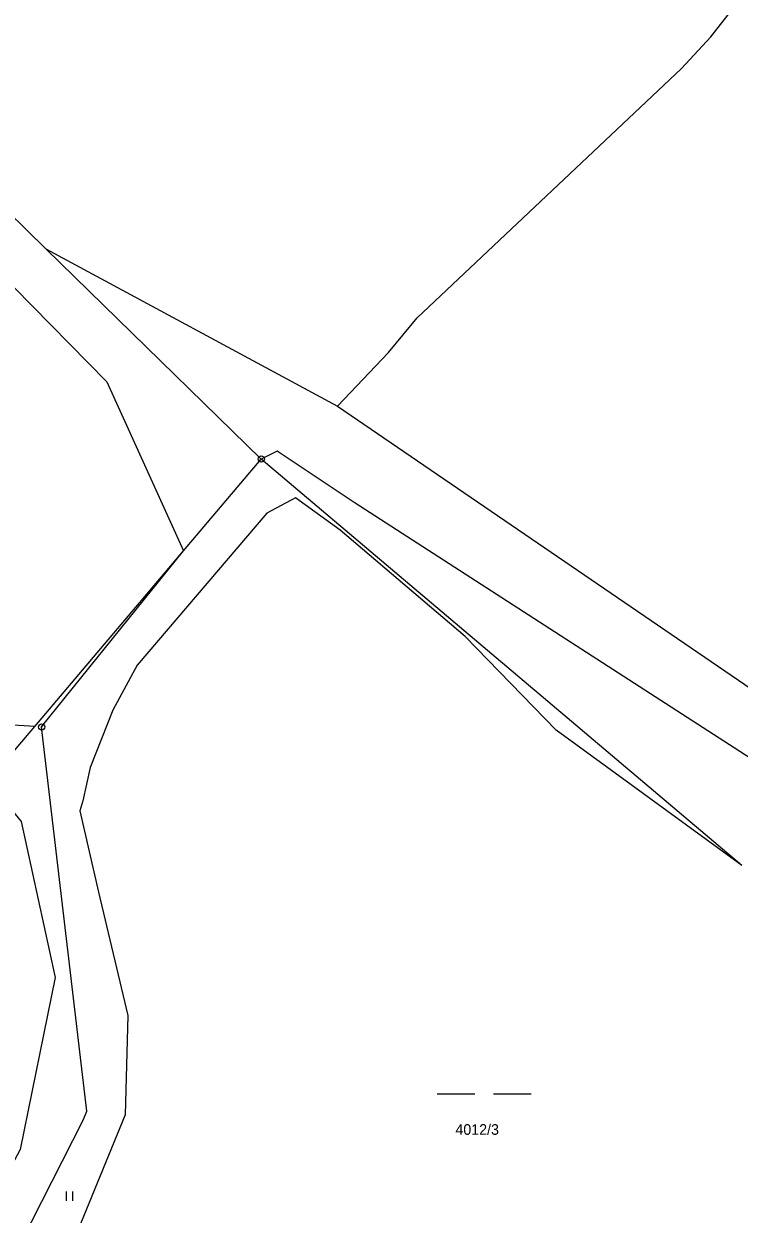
# Model space of a CAD drawing. Extents: x -733394 to -722299, y -1082822 to -1075049.
# Drawn here: x -727518.4 to -727404.2, y -1080319.1 to -1080129.1 of the extents above; entities that cross this region are included whole.
import ezdxf

# ---------------------------------------------------------------- set-up
doc = ezdxf.new("R2010")
doc.units = 0
for name, color, linetype in [('Hranice parcel', 7, 'Continuous'), ('Parcelní čísla', 7, 'Continuous'), ('Značky bodu BP', 7, 'Continuous'), ('Značky kultur', 7, 'Continuous')]:
    doc.layers.add(name, color=color, linetype=linetype)

msp = doc.modelspace()

# ---------------------------------------------------------------- linework, layer by layer
at = {"layer": 'Hranice parcel'}
for p, q in [((-727514.92, -1080165), (-727468.36, -1080190.16)), ((-727480.51, -1080198.57), (-727514.92, -1080165)), ((-727492.93, -1080213.23), (-727480.51, -1080198.57)), ((-727403.8, -1080263.45), (-727480.51, -1080198.57)), ((-727516.69, -1080241.27), (-727492.93, -1080213.23)), ((-727524.14, -1080250.06), (-727516.69, -1080241.27))]:
    msp.add_line(p, q, dxfattribs=at)
for points in [[(-727468.36, -1080190.16), (-727460.22, -1080181.58), (-727455.62, -1080176.03), (-727413.4, -1080136.24), (-727408.74, -1080131.18), (-727399.8, -1080119.73)], [(-727514.92, -1080165), (-727524.19, -1080155.96), (-727552.04, -1080138.31)], [(-727516.69, -1080241.27), (-727525.37, -1080240.73), (-727530.76, -1080232.44), (-727545.29, -1080196.73), (-727561.39, -1080168.05), (-727565.43, -1080157.25), (-727564.42, -1080151.89), (-727561.09, -1080148.63), (-727557.11, -1080147.79), (-727534.92, -1080156.01), (-727505.15, -1080186.24), (-727492.93, -1080213.23)], [(-727468.36, -1080190.16), (-727384.13, -1080247.66), (-727319.67, -1080176.42), (-727318.63, -1080175.17)], [(-727354.81, -1080273.91), (-727357.58, -1080271.96), (-727397.34, -1080249.65), (-727465.66, -1080205.49), (-727477.97, -1080197.34), (-727480.51, -1080198.57)], [(-727403.8, -1080263.45), (-727433.46, -1080241.88), (-727447.96, -1080226.89), (-727467.92, -1080209.94), (-727475.06, -1080204.77), (-727479.63, -1080207.19), (-727500.33, -1080231.48), (-727504.22, -1080238.64), (-727507.84, -1080247.84), (-727509.03, -1080253.13), (-727509.46, -1080254.74), (-727506.5, -1080267.72), (-727501.81, -1080287.4), (-727502.22, -1080303.25), (-727512.06, -1080327.15)], [(-727519.61, -1080409.47), (-727548.42, -1080384.36), (-727549.63, -1080383.17), (-727548.59, -1080382.02), (-727508.96, -1080304.12), (-727508.39, -1080302.69), (-727515.58, -1080241.34), (-727492.93, -1080213.23)], [(-727524.14, -1080250.06), (-727518.85, -1080256.45), (-727513.41, -1080281.32), (-727518.99, -1080308.77), (-727557.62, -1080381.31)]]:
    msp.add_lwpolyline(points, dxfattribs=at)
at = {"layer": 'Značky bodu BP'}
for centre, radius in [((-727480.51, -1080198.57), 0.5), ((-727480.51, -1080198.57), 0.5), ((-727480.51, -1080198.57), 0.0303), ((-727480.51, -1080198.57), 0.0303), ((-727515.58, -1080241.34), 0.5), ((-727515.58, -1080241.34), 0.5), ((-727515.58, -1080241.34), 0.5), ((-727515.58, -1080241.34), 0.5), ((-727515.58, -1080241.34), 0.0303), ((-727515.58, -1080241.34), 0.0303), ((-727515.58, -1080241.34), 0.0303), ((-727515.58, -1080241.34), 0.0303)]:
    msp.add_circle(centre, radius, dxfattribs=at)
at = {"layer": 'Značky kultur'}
for p, q in [((-727452.43, -1080299.93), (-727446.43, -1080299.93)), ((-727443.43, -1080299.93), (-727437.43, -1080299.93)), ((-727511.59, -1080316.99), (-727511.59, -1080315.49)), ((-727510.59, -1080316.99), (-727510.59, -1080315.49))]:
    msp.add_line(p, q, dxfattribs=at)

# ---------------------------------------------------------------- texts
at = {"layer": 'Parcelní čísla'}
msp.add_text('4012/3', height=1.7, dxfattribs=at).set_placement((-727449.52, -1080306.45))

doc.saveas('drawing.dxf')
